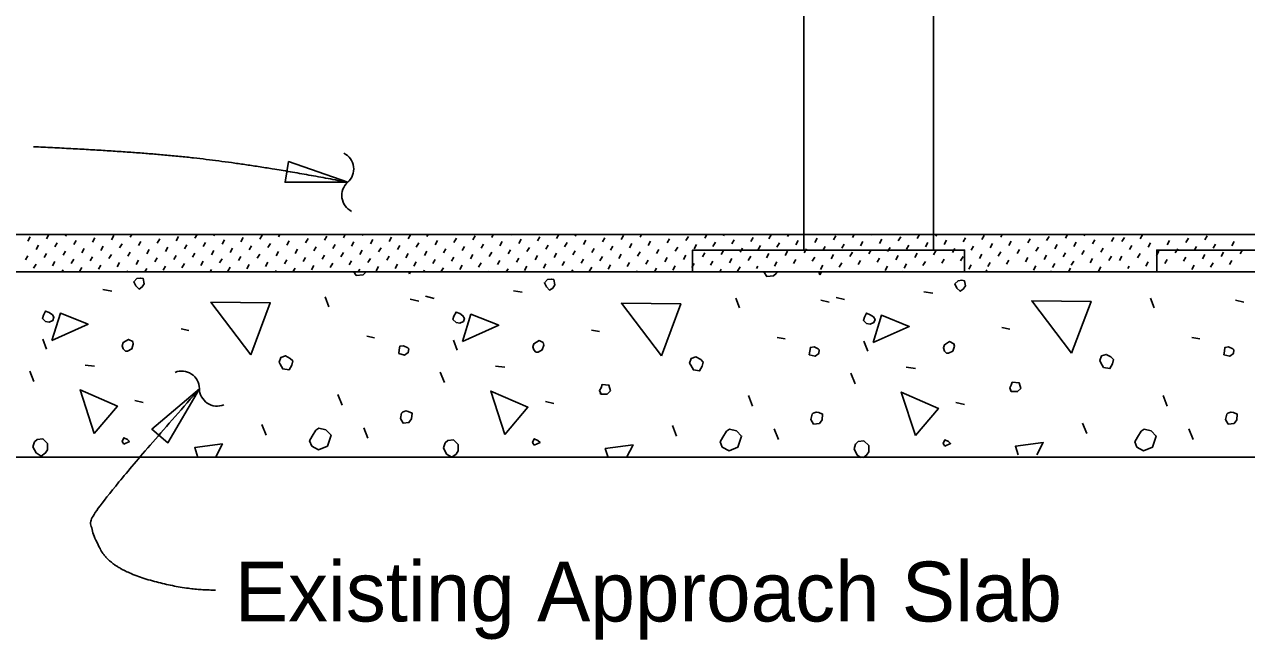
# Model space of a CAD drawing. Extents: x 1.5 to 68.7, y 0 to 31.1.
# Drawn here: x 10.034 to 14.152, y 9.621 to 11.693 of the extents above; entities that cross this region are included whole.
import ezdxf

# ---------------------------------------------------------------- set-up
doc = ezdxf.new("R2010")
doc.units = 0
for name, color, linetype in [('Dimension', 7, 'Continuous'), ('Miscellaneous', 7, 'Continuous'), ('TextStructures', 7, 'Continuous'), ('TrafBarrierConc', 7, 'Continuous')]:
    doc.layers.add(name, color=color, linetype=linetype)

msp = doc.modelspace()

# ---------------------------------------------------------------- linework, layer by layer
at = {"layer": 'Dimension'}
for points in [[(11.1237, 11.1609), (10.9243, 11.2307), (10.9124, 11.1611)], [(10.6245, 10.4656), (10.4635, 10.3289), (10.5175, 10.2835)]]:
    msp.add_lwpolyline(points, close=True, dxfattribs=at)
for centre, start, end in [((11.0841, 11.2055), 311.5733, 63.3005), ((11.1632, 11.1163), 131.5733, 243.3005), ((10.5642, 10.4655), 0.5042, 112.2314), ((10.6834, 10.4666), 180.5042, 292.2314)]:
    msp.add_arc(centre, 0.0596, start, end, dxfattribs=at)
for points in [[(10.0652, 11.2806), (10.4382, 11.2638), (10.858, 11.2123), (11.1236, 11.1609)], [(10.6244, 10.4656), (10.2576, 10.0524), (10.2576, 9.9848), (10.3251, 9.8601), (10.5693, 9.7873), (10.6784, 9.7873)]]:
    msp.add_open_spline(points, degree=2, dxfattribs=at)
at = {"layer": 'Miscellaneous'}
for p, q in [((12.6601, 10.9324), (12.6601, 11.8211)), ((13.0976, 10.9324), (13.0976, 11.8211)), ((10.0455, 10.9627), (10.0536, 10.9767)), ((10.109, 10.9708), (10.1169, 10.9845)), ((10.1367, 10.9431), (10.1448, 10.9571)), ((10.1725, 10.9789), (10.1757, 10.9845)), ((10.2002, 10.9512), (10.2083, 10.9652)), ((10.2637, 10.9593), (10.2718, 10.9733)), ((10.3272, 10.9674), (10.3353, 10.9814)), ((10.3549, 10.9397), (10.363, 10.9537)), ((10.3907, 10.9755), (10.3959, 10.9845)), ((10.4184, 10.9479), (10.4265, 10.9618)), ((10.4542, 10.9836), (10.4547, 10.9845)), ((10.4819, 10.956), (10.49, 10.9699)), ((10.5454, 10.9641), (10.5535, 10.978)), ((10.6089, 10.9722), (10.616, 10.9845)), ((10.6366, 10.9445), (10.6447, 10.9585)), ((10.6724, 10.9803), (10.6748, 10.9845)), ((10.7, 10.9526), (10.7082, 10.9666)), ((10.7635, 10.9607), (10.7716, 10.9747)), ((10.827, 10.9688), (10.8351, 10.9828)), ((10.8547, 10.9411), (10.8628, 10.9551)), ((10.8905, 10.9769), (10.8949, 10.9845)), ((10.9182, 10.9492), (10.9263, 10.9632)), ((10.9817, 10.9573), (10.9898, 10.9713)), ((11.0452, 10.9654), (11.0533, 10.9794)), ((11.1087, 10.9735), (11.1151, 10.9845)), ((11.1364, 10.9458), (11.1445, 10.9598)), ((11.1722, 10.9816), (11.1739, 10.9845)), ((11.1999, 10.9539), (11.208, 10.9679)), ((11.2634, 10.962), (11.2715, 10.976)), ((11.3269, 10.9701), (11.335, 10.9841)), ((11.3546, 10.9424), (11.3627, 10.9564)), ((11.3904, 10.9782), (11.394, 10.9845)), ((11.4181, 10.9505), (11.4262, 10.9645)), ((11.4815, 10.9586), (11.4897, 10.9726)), ((11.545, 10.9667), (11.5531, 10.9807)), ((11.6085, 10.9748), (11.6141, 10.9845)), ((11.6362, 10.9471), (11.6443, 10.9611)), ((11.672, 10.9829), (11.6729, 10.9845)), ((11.6997, 10.9552), (11.7078, 10.9692)), ((11.7632, 10.9633), (11.7713, 10.9773)), ((11.8267, 10.9714), (11.8343, 10.9845)), ((11.8544, 10.9437), (11.8625, 10.9577)), ((11.8902, 10.9795), (11.8931, 10.9845)), ((11.9179, 10.9518), (11.926, 10.9658)), ((11.9814, 10.9599), (11.9895, 10.9739)), ((12.0449, 10.968), (12.053, 10.982)), ((12.0726, 10.9403), (12.0807, 10.9543)), ((12.1084, 10.9761), (12.1132, 10.9845)), ((12.1361, 10.9484), (12.1442, 10.9624)), ((12.1719, 10.9842), (12.172, 10.9845)), ((12.1996, 10.9565), (12.2077, 10.9705)), ((12.263, 10.9646), (12.2712, 10.9786)), ((12.3265, 10.9727), (12.3333, 10.9845)), ((12.3542, 10.9451), (12.3623, 10.959)), ((12.39, 10.9808), (12.3921, 10.9845)), ((12.4177, 10.9532), (12.4258, 10.9671)), ((12.4812, 10.9613), (12.4893, 10.9753)), ((12.5421, 10.9701), (12.5502, 10.9841)), ((12.5698, 10.9424), (12.5779, 10.9564)), ((12.6056, 10.9782), (12.6093, 10.9845)), ((12.6333, 10.9505), (12.6414, 10.9645)), ((12.6968, 10.9586), (12.7049, 10.9726)), ((12.7603, 10.9667), (12.7684, 10.9807)), ((12.8238, 10.9748), (12.8294, 10.9845)), ((12.8515, 10.9471), (12.8596, 10.9611)), ((12.8873, 10.9829), (12.8882, 10.9845)), ((12.915, 10.9552), (12.9231, 10.9692)), ((12.9785, 10.9633), (12.9866, 10.9773)), ((13.042, 10.9714), (13.0495, 10.9845)), ((13.0697, 10.9437), (13.0778, 10.9577)), ((13.1055, 10.9795), (13.1083, 10.9845)), ((13.1332, 10.9518), (13.1413, 10.9658)), ((13.1966, 10.9599), (13.2047, 10.9739)), ((13.2601, 10.968), (13.2682, 10.982)), ((13.2878, 10.9403), (13.2959, 10.9543)), ((13.3236, 10.9761), (13.3285, 10.9845)), ((13.3513, 10.9484), (13.3594, 10.9624)), ((13.3871, 10.9842), (13.3873, 10.9845)), ((13.4148, 10.9565), (13.4229, 10.9705)), ((13.4783, 10.9646), (13.4864, 10.9786)), ((13.5418, 10.9727), (13.5486, 10.9845)), ((13.5695, 10.9451), (13.5776, 10.959)), ((13.6053, 10.9808), (13.6074, 10.9845)), ((13.633, 10.9532), (13.6411, 10.9671)), ((13.6965, 10.9613), (13.7046, 10.9753)), ((13.7322, 10.9613), (13.7403, 10.9753)), ((13.7931, 10.9701), (13.8013, 10.9841)), ((13.8208, 10.9424), (13.8289, 10.9564)), ((13.8843, 10.9505), (13.8924, 10.9645)), ((13.9478, 10.9586), (13.9559, 10.9726)), ((14.0113, 10.9667), (14.0194, 10.9807)), ((14.1025, 10.9471), (14.1106, 10.9611)), ((10.0374, 10.8992), (10.0455, 10.9132)), ((10.0732, 10.935), (10.0813, 10.949)), ((10.1009, 10.9073), (10.109, 10.9213)), ((10.1644, 10.9154), (10.1725, 10.9294)), ((10.2279, 10.9235), (10.236, 10.9375)), ((10.2914, 10.9316), (10.2995, 10.9456)), ((10.3191, 10.904), (10.3272, 10.9179)), ((10.3826, 10.9121), (10.3907, 10.926)), ((10.4461, 10.9202), (10.4542, 10.9342)), ((10.5096, 10.9283), (10.5177, 10.9423)), ((10.5373, 10.9006), (10.5454, 10.9146)), ((10.5731, 10.9364), (10.5812, 10.9504)), ((10.6008, 10.9087), (10.6089, 10.9227)), ((10.6643, 10.9168), (10.6724, 10.9308)), ((10.7277, 10.9249), (10.7358, 10.9389)), ((10.7912, 10.933), (10.7993, 10.947)), ((10.8189, 10.9053), (10.827, 10.9193)), ((10.8824, 10.9134), (10.8905, 10.9274)), ((10.9459, 10.9215), (10.954, 10.9355)), ((11.0094, 10.9296), (11.0175, 10.9436)), ((11.0371, 10.9019), (11.0452, 10.9159)), ((11.0729, 10.9377), (11.081, 10.9517)), ((11.1006, 10.91), (11.1087, 10.924)), ((11.1641, 10.9181), (11.1722, 10.9321)), ((11.2276, 10.9262), (11.2357, 10.9402)), ((11.2553, 10.8985), (11.2634, 10.9125)), ((11.2911, 10.9343), (11.2992, 10.9483)), ((11.3188, 10.9066), (11.3269, 10.9206)), ((11.3823, 10.9147), (11.3904, 10.9287)), ((11.4458, 10.9228), (11.4539, 10.9368)), ((11.5092, 10.9309), (11.5173, 10.9449)), ((11.5369, 10.9032), (11.545, 10.9172)), ((11.5727, 10.939), (11.5808, 10.953)), ((11.6004, 10.9113), (11.6085, 10.9253)), ((11.6639, 10.9194), (11.672, 10.9334)), ((11.7274, 10.9275), (11.7355, 10.9415)), ((11.7551, 10.8998), (11.7632, 10.9138)), ((11.7909, 10.9356), (11.799, 10.9496)), ((11.8186, 10.9079), (11.8267, 10.9219)), ((11.8821, 10.916), (11.8902, 10.93)), ((11.9456, 10.9241), (11.9537, 10.9381)), ((12.0091, 10.9322), (12.0172, 10.9462)), ((12.0368, 10.9045), (12.0449, 10.9185)), ((12.1003, 10.9126), (12.1084, 10.9266)), ((12.1638, 10.9207), (12.1719, 10.9347)), ((12.2273, 10.9288), (12.2354, 10.9428)), ((12.2549, 10.9012), (12.263, 10.9151)), ((12.2907, 10.9369), (12.2988, 10.9509)), ((12.3184, 10.9093), (12.3265, 10.9232)), ((12.3819, 10.9174), (12.39, 10.9314)), ((12.4454, 10.9255), (12.4535, 10.9395)), ((12.5063, 10.9343), (12.5144, 10.9483)), ((12.534, 10.9066), (12.5421, 10.9206)), ((12.5975, 10.9147), (12.6056, 10.9287)), ((12.661, 10.9228), (12.6691, 10.9368)), ((12.7245, 10.9309), (12.7326, 10.9449)), ((12.7522, 10.9032), (12.7603, 10.9172)), ((12.788, 10.939), (12.7961, 10.953)), ((12.8157, 10.9113), (12.8238, 10.9253)), ((12.8792, 10.9194), (12.8873, 10.9334)), ((12.9427, 10.9275), (12.9508, 10.9415)), ((12.9704, 10.8998), (12.9785, 10.9138)), ((13.0062, 10.9356), (13.0143, 10.9496)), ((13.0339, 10.9079), (13.042, 10.9219)), ((13.0974, 10.916), (13.1055, 10.93)), ((13.1608, 10.9241), (13.169, 10.9381)), ((13.2243, 10.9322), (13.2324, 10.9462)), ((13.252, 10.9045), (13.2601, 10.9185)), ((13.3155, 10.9126), (13.3236, 10.9266)), ((13.379, 10.9207), (13.3871, 10.9347)), ((13.4425, 10.9288), (13.4506, 10.9428)), ((13.4702, 10.9012), (13.4783, 10.9151)), ((13.506, 10.9369), (13.5141, 10.9509)), ((13.5337, 10.9093), (13.5418, 10.9232)), ((13.5972, 10.9174), (13.6053, 10.9314)), ((13.6607, 10.9255), (13.6688, 10.9395)), ((13.7574, 10.9343), (13.7655, 10.9483)), ((13.785, 10.9066), (13.7931, 10.9206)), ((13.8485, 10.9147), (13.8566, 10.9287)), ((13.912, 10.9228), (13.9201, 10.9368)), ((13.9755, 10.9309), (13.9836, 10.9449)), ((14.0032, 10.9032), (14.0113, 10.9172)), ((14.039, 10.939), (14.0471, 10.953)), ((14.0667, 10.9113), (14.0748, 10.9253)), ((14.1302, 10.9194), (14.1383, 10.9334)), ((10.0651, 10.8715), (10.0732, 10.8855)), ((10.1286, 10.8796), (10.1367, 10.8936)), ((10.1921, 10.8877), (10.2002, 10.9017)), ((10.2198, 10.8601), (10.2279, 10.874)), ((10.2556, 10.8958), (10.2637, 10.9098)), ((10.2833, 10.8682), (10.2914, 10.8821)), ((10.3468, 10.8763), (10.3549, 10.8903)), ((10.4103, 10.8844), (10.4184, 10.8984)), ((10.4738, 10.8925), (10.4819, 10.9065)), ((10.5015, 10.8648), (10.5096, 10.8788)), ((10.565, 10.8729), (10.5731, 10.8869)), ((10.6285, 10.881), (10.6366, 10.895)), ((10.6919, 10.8891), (10.7, 10.9031)), ((10.7196, 10.8614), (10.7277, 10.8754)), ((10.7554, 10.8972), (10.7635, 10.9112)), ((10.7831, 10.8695), (10.7912, 10.8835)), ((10.8466, 10.8776), (10.8547, 10.8916)), ((10.9101, 10.8857), (10.9182, 10.8997)), ((10.9387, 10.8595), (10.9459, 10.872)), ((10.9736, 10.8938), (10.9817, 10.9078)), ((11.0013, 10.8661), (11.0094, 10.8801)), ((11.0648, 10.8742), (11.0729, 10.8882)), ((11.1283, 10.8823), (11.1364, 10.8963)), ((11.1918, 10.8904), (11.1999, 10.9044)), ((11.2195, 10.8627), (11.2276, 10.8767)), ((11.283, 10.8708), (11.2911, 10.8848)), ((11.3465, 10.8789), (11.3546, 10.8929)), ((11.41, 10.887), (11.4181, 10.901)), ((11.4377, 10.8595), (11.4458, 10.8733)), ((11.4734, 10.8951), (11.4815, 10.9091)), ((11.5011, 10.8674), (11.5092, 10.8814)), ((11.5646, 10.8755), (11.5727, 10.8895)), ((11.6281, 10.8836), (11.6362, 10.8976)), ((11.6916, 10.8917), (11.6997, 10.9057)), ((11.7193, 10.864), (11.7274, 10.878)), ((11.7828, 10.8721), (11.7909, 10.8861)), ((11.8463, 10.8802), (11.8544, 10.8942)), ((11.9098, 10.8883), (11.9179, 10.9023)), ((11.9375, 10.8606), (11.9456, 10.8746)), ((11.9733, 10.8964), (11.9814, 10.9104)), ((12.001, 10.8687), (12.0091, 10.8827)), ((12.0645, 10.8768), (12.0726, 10.8908)), ((12.128, 10.8849), (12.1361, 10.8989)), ((12.1569, 10.8595), (12.1638, 10.8712)), ((12.1915, 10.893), (12.1996, 10.907)), ((12.2191, 10.8654), (12.2273, 10.8793)), ((12.2826, 10.8735), (12.2907, 10.8875)), ((12.3461, 10.8816), (12.3542, 10.8956)), ((12.4096, 10.8897), (12.4177, 10.9037)), ((12.4373, 10.862), (12.4454, 10.876)), ((12.4731, 10.8978), (12.4812, 10.9118)), ((12.5008, 10.8701), (12.5058, 10.8788)), ((12.5617, 10.8789), (12.5698, 10.8929)), ((12.6252, 10.887), (12.6333, 10.901)), ((12.6887, 10.8951), (12.6968, 10.9091)), ((12.7164, 10.8674), (12.7245, 10.8814)), ((12.7799, 10.8755), (12.788, 10.8895)), ((12.8434, 10.8836), (12.8515, 10.8976)), ((12.9069, 10.8917), (12.915, 10.9057)), ((12.9346, 10.864), (12.9427, 10.878)), ((12.9981, 10.8721), (13.0062, 10.8861)), ((13.0616, 10.8802), (13.0697, 10.8942)), ((13.1251, 10.8883), (13.1332, 10.9023)), ((13.1885, 10.8964), (13.1966, 10.9104)), ((13.2162, 10.8687), (13.2243, 10.8827)), ((13.2797, 10.8768), (13.2878, 10.8908)), ((13.3432, 10.8849), (13.3513, 10.8989)), ((13.4067, 10.893), (13.4148, 10.907)), ((13.4344, 10.8654), (13.4425, 10.8793)), ((13.4979, 10.8735), (13.506, 10.8875)), ((13.552, 10.8595), (13.5588, 10.8712)), ((13.5614, 10.8816), (13.5695, 10.8956)), ((13.6249, 10.8897), (13.633, 10.9037)), ((13.6526, 10.862), (13.6607, 10.876)), ((13.6884, 10.8978), (13.6965, 10.9118)), ((13.7241, 10.8978), (13.7322, 10.9118)), ((13.7518, 10.8701), (13.7569, 10.8788)), ((13.8127, 10.8789), (13.8208, 10.8929)), ((13.8762, 10.887), (13.8843, 10.901)), ((13.9397, 10.8951), (13.9478, 10.9091)), ((13.9674, 10.8674), (13.9755, 10.8814)), ((14.0309, 10.8755), (14.039, 10.8895)), ((14.0944, 10.8836), (14.1025, 10.8976)), ((10.1607, 10.8595), (10.1644, 10.8659)), ((10.3808, 10.8595), (10.3826, 10.8626)), ((10.4396, 10.8595), (10.4461, 10.8707)), ((10.6597, 10.8595), (10.6643, 10.8673)), ((10.8799, 10.8595), (10.8824, 10.8639)), ((11.1, 10.8595), (11.1006, 10.8605)), ((11.1588, 10.8595), (11.1641, 10.8686)), ((11.3789, 10.8595), (11.3823, 10.8652)), ((11.5991, 10.8595), (11.6004, 10.8618)), ((11.6579, 10.8595), (11.6639, 10.8699)), ((11.878, 10.8595), (11.8821, 10.8665)), ((12.0981, 10.8595), (12.1003, 10.8631)), ((12.3183, 10.8595), (12.3184, 10.8598)), ((12.3771, 10.8595), (12.3819, 10.8679)), ((12.9941, 10.8595), (12.9955, 10.8618)), ((13.2731, 10.8595), (13.2772, 10.8665)), ((13.4932, 10.8595), (13.4953, 10.8631)), ((10.2984, 10.7994), (10.3285, 10.7941)), ((11.6817, 10.7958), (11.7117, 10.7905)), ((13.065, 10.7923), (13.095, 10.787)), ((11.0603, 10.741), (11.0479, 10.7746)), ((11.3343, 10.7676), (11.3626, 10.7605)), ((11.386, 10.7768), (11.4143, 10.7698)), ((12.4436, 10.7375), (12.4312, 10.7711)), ((12.7176, 10.764), (12.7459, 10.757)), ((12.7693, 10.7733), (12.7976, 10.7662)), ((13.8407, 10.7375), (13.8283, 10.7711)), ((14.1147, 10.764), (14.143, 10.757)), ((10.5618, 10.6668), (10.5883, 10.6615)), ((13.3274, 10.6715), (13.354, 10.6662)), ((10.1088, 10.5992), (10.0964, 10.6328)), ((11.1876, 10.6421), (11.2141, 10.6368)), ((11.4921, 10.5957), (11.4797, 10.6292)), ((11.9451, 10.6633), (11.9716, 10.658)), ((12.5709, 10.6385), (12.5974, 10.6332)), ((12.8754, 10.5921), (12.863, 10.6257)), ((13.968, 10.6385), (13.9945, 10.6332)), ((10.2383, 10.5448), (10.2701, 10.5413)), ((10.0664, 10.4896), (10.0522, 10.5249)), ((11.4497, 10.486), (11.4355, 10.5214)), ((11.6216, 10.5413), (11.6534, 10.5378)), ((12.8329, 10.4825), (12.8188, 10.5179)), ((13.0049, 10.5378), (13.0367, 10.5342)), ((10.4062, 10.4264), (10.4345, 10.4193)), ((11.1045, 10.4105), (11.0904, 10.4458)), ((11.7895, 10.4229), (11.8178, 10.4158)), ((12.4878, 10.4069), (12.4736, 10.4423)), ((13.1728, 10.4193), (13.2011, 10.4122)), ((13.8849, 10.4069), (13.8707, 10.4423)), ((10.8482, 10.3097), (10.834, 10.3451)), ((12.2315, 10.3062), (12.2173, 10.3415)), ((13.6138, 10.3144), (13.5997, 10.3497)), ((11.1916, 10.2987), (11.1774, 10.334)), ((12.5748, 10.2951), (12.5607, 10.3305)), ((13.9719, 10.2951), (13.9578, 10.3305))]:
    msp.add_line(p, q, dxfattribs=at)
for points in [[(12.2853, 10.8595), (13.2019, 10.8595), (13.2019, 10.9324), (12.2853, 10.9324)], [(13.8495, 10.8595), (14.7661, 10.8595), (14.7661, 10.9324), (13.8495, 10.9324)]]:
    msp.add_lwpolyline(points, close=True, dxfattribs=at)
for points in [[(10.4098, 10.8118), (10.4204, 10.8012), (10.431, 10.8082), (10.4381, 10.8188), (10.4345, 10.8365), (10.4257, 10.8383), (10.4133, 10.8365), (10.4027, 10.8259), (10.4098, 10.8118)], [(11.1446, 10.8594), (11.1522, 10.8471), (11.1752, 10.8489), (11.1841, 10.8577), (11.1857, 10.8594)], [(11.3312, 10.8529), (11.3291, 10.8594)], [(11.3346, 10.8594), (11.3312, 10.8529)], [(11.793, 10.8082), (11.8037, 10.7976), (11.8143, 10.8047), (11.8213, 10.8153), (11.8178, 10.833), (11.809, 10.8347), (11.7966, 10.833), (11.786, 10.8224), (11.793, 10.8082)], [(12.5257, 10.8594), (12.5355, 10.8436), (12.5585, 10.8453), (12.5673, 10.8542), (12.5726, 10.8594)], [(12.7145, 10.8493), (12.7112, 10.8594)], [(12.7197, 10.8594), (12.7145, 10.8493)], [(13.1763, 10.8047), (13.1869, 10.7941), (13.1975, 10.8012), (13.2046, 10.8118), (13.2011, 10.8294), (13.1922, 10.8312), (13.1799, 10.8294), (13.1693, 10.8188), (13.1763, 10.8047)], [(10.7969, 10.5802), (10.6626, 10.757), (10.8623, 10.7552), (10.7969, 10.5802)], [(12.1802, 10.5766), (12.0458, 10.7534), (12.2456, 10.7517), (12.1802, 10.5766)], [(13.5625, 10.5849), (13.4282, 10.7616), (13.628, 10.7599), (13.5625, 10.5849)], [(10.1053, 10.692), (10.1176, 10.6902), (10.13, 10.6955), (10.1336, 10.7061), (10.1283, 10.715), (10.1176, 10.722), (10.1053, 10.7273), (10.0982, 10.7132), (10.0947, 10.7026), (10.1053, 10.692)], [(10.1269, 10.6279), (10.1552, 10.7198), (10.2489, 10.6827), (10.1269, 10.6279)], [(11.4885, 10.6885), (11.5009, 10.6867), (11.5133, 10.692), (11.5168, 10.7026), (11.5115, 10.7114), (11.5009, 10.7185), (11.4885, 10.7238), (11.4815, 10.7097), (11.4779, 10.6991), (11.4885, 10.6885)], [(11.5102, 10.6244), (11.5385, 10.7163), (11.6322, 10.6792), (11.5102, 10.6244)], [(12.8718, 10.6849), (12.8842, 10.6832), (12.8966, 10.6885), (12.9001, 10.6991), (12.8948, 10.7079), (12.8842, 10.715), (12.8718, 10.7203), (12.8648, 10.7061), (12.8612, 10.6955), (12.8718, 10.6849)], [(12.8935, 10.6208), (12.9218, 10.7128), (13.0155, 10.6756), (12.8935, 10.6208)], [(10.3744, 10.5926), (10.3815, 10.5926), (10.3956, 10.5996), (10.4009, 10.6155), (10.3992, 10.6244), (10.385, 10.6314), (10.3673, 10.6208), (10.3638, 10.6102), (10.3673, 10.5996), (10.3744, 10.5926)], [(11.7577, 10.589), (11.7648, 10.589), (11.7789, 10.5961), (11.7842, 10.612), (11.7824, 10.6208), (11.7683, 10.6279), (11.7506, 10.6173), (11.7471, 10.6067), (11.7506, 10.5961), (11.7577, 10.589)], [(13.141, 10.5855), (13.148, 10.5855), (13.1622, 10.5926), (13.1675, 10.6085), (13.1657, 10.6173), (13.1516, 10.6244), (13.1339, 10.6138), (13.1304, 10.6032), (13.1339, 10.5926), (13.141, 10.5855)], [(11.2954, 10.5837), (11.3149, 10.5784), (11.3272, 10.5873), (11.329, 10.5996), (11.3255, 10.6032), (11.3113, 10.6102), (11.299, 10.6085), (11.2972, 10.5961), (11.2954, 10.5837)], [(12.6787, 10.5802), (12.6981, 10.5749), (12.7105, 10.5837), (12.7123, 10.5961), (12.7087, 10.5996), (12.6946, 10.6067), (12.6822, 10.6049), (12.6805, 10.5926), (12.6787, 10.5802)], [(14.0758, 10.5802), (14.0952, 10.5749), (14.1076, 10.5837), (14.1094, 10.5961), (14.1058, 10.5996), (14.0917, 10.6067), (14.0793, 10.6049), (14.0776, 10.5926), (14.0758, 10.5802)], [(10.8959, 10.5484), (10.9047, 10.5325), (10.926, 10.5289), (10.9348, 10.5448), (10.9383, 10.559), (10.9295, 10.5678), (10.9136, 10.5766), (10.8977, 10.5713), (10.8924, 10.5554), (10.8959, 10.5484)], [(12.2792, 10.5448), (12.288, 10.5289), (12.3092, 10.5254), (12.3181, 10.5413), (12.3216, 10.5554), (12.3128, 10.5643), (12.2969, 10.5731), (12.281, 10.5678), (12.2756, 10.5519), (12.2792, 10.5448)], [(13.6615, 10.553), (13.6704, 10.5371), (13.6916, 10.5336), (13.7004, 10.5495), (13.704, 10.5636), (13.6951, 10.5725), (13.6792, 10.5813), (13.6633, 10.576), (13.658, 10.5601), (13.6615, 10.553)], [(10.2697, 10.3146), (10.2219, 10.4613), (10.3475, 10.4065), (10.2697, 10.3146)], [(11.9769, 10.4476), (11.9981, 10.4476), (12.0087, 10.4582), (12.0034, 10.4777), (11.9804, 10.4794), (11.9769, 10.4688), (11.9716, 10.46), (11.9769, 10.4476), (11.9734, 10.4511)], [(13.3593, 10.4558), (13.3805, 10.4558), (13.3911, 10.4664), (13.3858, 10.4859), (13.3628, 10.4876), (13.3593, 10.477), (13.354, 10.4682), (13.3593, 10.4558), (13.3557, 10.4593)], [(11.653, 10.311), (11.6052, 10.4578), (11.7307, 10.403), (11.653, 10.311)], [(13.0362, 10.3075), (12.9885, 10.4542), (13.114, 10.3994), (13.0362, 10.3075)], [(11.3012, 10.3658), (11.31, 10.3499), (11.3294, 10.3517), (11.3383, 10.3641), (11.3401, 10.3835), (11.3277, 10.3888), (11.3188, 10.3906), (11.3082, 10.3871), (11.3047, 10.3835), (11.3012, 10.3658)], [(12.6844, 10.3623), (12.6933, 10.3464), (12.7127, 10.3482), (12.7216, 10.3605), (12.7233, 10.38), (12.711, 10.3853), (12.7021, 10.3871), (12.6915, 10.3835), (12.688, 10.38), (12.6844, 10.3623)], [(14.0815, 10.3623), (14.0904, 10.3464), (14.1098, 10.3482), (14.1187, 10.3605), (14.1204, 10.38), (14.108, 10.3853), (14.0992, 10.3871), (14.0886, 10.3835), (14.0851, 10.38), (14.0815, 10.3623)], [(10.0628, 10.2704), (10.0735, 10.2492), (10.0911, 10.2386), (10.1053, 10.2492), (10.1123, 10.2598), (10.1123, 10.281), (10.0964, 10.2969), (10.077, 10.2951), (10.0681, 10.2863), (10.0628, 10.2704)], [(10.3687, 10.2792), (10.3881, 10.2881), (10.381, 10.2951), (10.3687, 10.3004), (10.3634, 10.2881), (10.3687, 10.2792)], [(11.002, 10.2726), (11.025, 10.2602), (11.055, 10.2726), (11.0674, 10.3097), (11.0497, 10.3274), (11.0267, 10.3327), (11.0161, 10.3256), (11.0037, 10.3062), (10.9949, 10.2903), (11.002, 10.2726)], [(11.7519, 10.2757), (11.7714, 10.2845), (11.7643, 10.2916), (11.7519, 10.2969), (11.7466, 10.2845), (11.7519, 10.2757)], [(12.3852, 10.2691), (12.4082, 10.2567), (12.4383, 10.2691), (12.4507, 10.3062), (12.433, 10.3239), (12.41, 10.3292), (12.3994, 10.3221), (12.387, 10.3026), (12.3782, 10.2867), (12.3852, 10.2691)], [(13.7823, 10.2691), (13.8053, 10.2567), (13.8354, 10.2691), (13.8477, 10.3062), (13.8301, 10.3239), (13.8071, 10.3292), (13.7965, 10.3221), (13.7841, 10.3026), (13.7753, 10.2867), (13.7823, 10.2691)], [(10.6183, 10.2344), (10.6078, 10.2673), (10.7015, 10.2797), (10.6782, 10.2344)], [(11.4461, 10.2668), (11.4567, 10.2456), (11.4744, 10.235), (11.4885, 10.2456), (11.4956, 10.2562), (11.4956, 10.2775), (11.4797, 10.2934), (11.4603, 10.2916), (11.4514, 10.2828), (11.4461, 10.2668)], [(12.0005, 10.2344), (11.991, 10.2638), (12.0847, 10.2761), (12.0633, 10.2344)], [(12.8616, 10.2344), (12.8718, 10.2421), (12.8789, 10.2527), (12.8789, 10.2739), (12.863, 10.2898), (12.8435, 10.2881), (12.8347, 10.2792), (12.8294, 10.2633)], [(12.8294, 10.2633), (12.84, 10.2421), (12.8528, 10.2344)], [(13.1352, 10.2721), (13.1547, 10.281), (13.1476, 10.2881), (13.1352, 10.2934), (13.1299, 10.281), (13.1352, 10.2721)], [(13.3828, 10.2427), (13.3734, 10.272), (13.4671, 10.2843), (13.4456, 10.2427)]]:
    msp.add_lwpolyline(points, dxfattribs=at)
at = {"layer": 'TrafBarrierConc'}
for p, q in [((3.8717, 10.9845), (18.1441, 10.9845)), ((5.8718, 10.8595), (11.8162, 10.8595)), ((11.8162, 10.8595), (18.1441, 10.8595)), ((9.0917, 10.2345), (18.1442, 10.2345))]:
    msp.add_line(p, q, dxfattribs=at)

# ---------------------------------------------------------------- texts
at = {"layer": 'TextStructures'}
msp.add_text('Existing Approach Slab', height=0.2016, dxfattribs=at).set_placement((10.7426, 9.6816))

doc.saveas('drawing.dxf')
